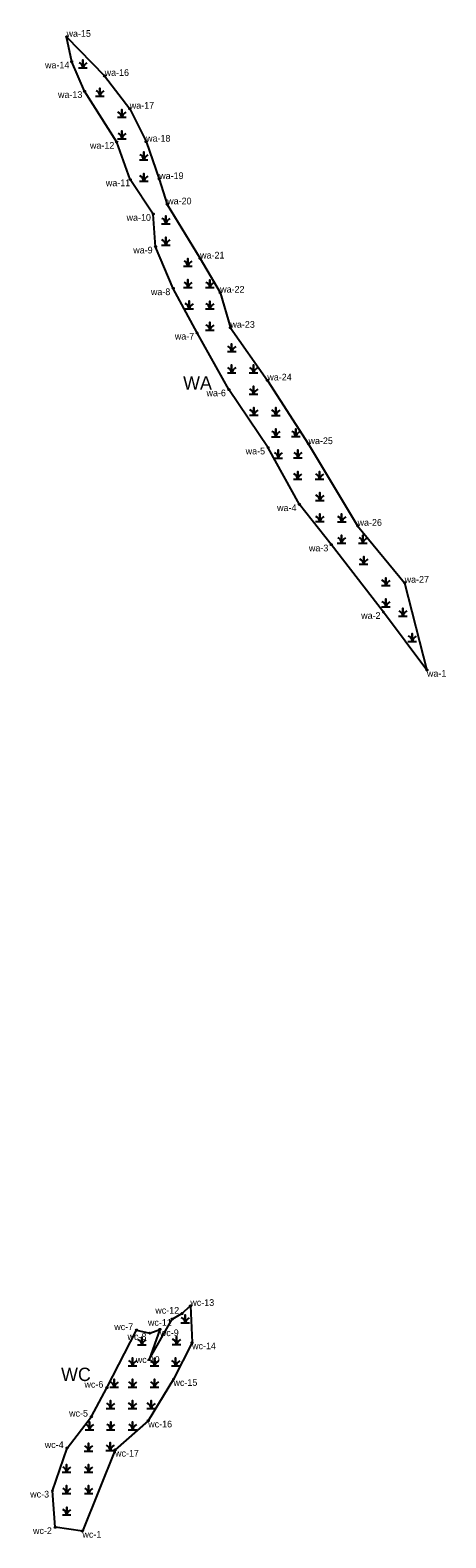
# Model space of a CAD drawing. Extents: x 1623201 to 1624143, y 886383 to 888508.
# Drawn here: x 1623832 to 1624143, y 886383 to 887511 of the extents above; entities that cross this region are included whole.
import ezdxf

# ---------------------------------------------------------------- set-up
doc = ezdxf.new("R2010")
doc.units = 0
for name, color, linetype in [('BR0168_Potential__x0020__Non__x002D__wetland__x0020__WOUS__x0020____x0028__Streams__x0029__', 7, 'Continuous'), ('BR0168_Potential__x0020__Non__x002D__wetland__x0020__WOUS__x0020____x0028__Surface__x0020__Waters__x0029__', 7, 'Continuous'), ('BR0168_Potential_Wetland_WOUS', 7, 'Continuous'), ('Default', 7, 'Continuous'), ('Exist Structure Major Bridge WW', 7, 'Continuous')]:
    doc.layers.add(name, color=color, linetype=linetype)

# ---------------------------------------------------------------- blocks, each defined once
blk = doc.blocks.new('SurveyPointCell')
at = {"layer": 'Default'}
for p, q in [((-0.5, 0), (0.5, 0)), ((0, -0.5), (0, 0.5))]:
    blk.add_line(p, q, dxfattribs=at)
blk.add_circle((0, 0), 0.5, dxfattribs=at)

msp = doc.modelspace()

# ---------------------------------------------------------------- linework, layer by layer
at = {"layer": 'BR0168_Potential_Wetland_WOUS'}
for points in [[(1624128.6, 887032.3), (1624096.1, 887075.6), (1624057, 887126.1), (1624033.2, 887156.2), (1624009.8, 887198.6), (1623980.5, 887242.1), (1623956.7, 887284.5), (1623938.8, 887317.7), (1623925.6, 887348.9), (1623923.9, 887373.3), (1623906.7, 887399.2), (1623896.5, 887427.2), (1623872.5, 887465.2), (1623862.9, 887487.3), (1623859, 887505.9), (1623887.5, 887476.7), (1623906.3, 887452.1), (1623918.5, 887427.5), (1623928.3, 887399.5), (1623934.3, 887380.6), (1623958.9, 887340.1), (1623973.9, 887314.6), (1623981.6, 887288.3), (1624009.2, 887248.9), (1624040, 887201.3), (1624076.7, 887140.2), (1624111.9, 887097.6)], [(1623870.9, 886388.4), (1623850.6, 886391.2), (1623848.5, 886418.5), (1623859.4, 886450.5), (1623877.6, 886474), (1623889.2, 886495.6), (1623911.4, 886538.7), (1623921.3, 886536.4), (1623928.8, 886539.2), (1623920.8, 886516.6), (1623938.1, 886546.9), (1623945.3, 886551), (1623951.6, 886556.8), (1623952.9, 886529.4), (1623939, 886502), (1623920.1, 886470.9), (1623895.3, 886449.1)]]:
    msp.add_lwpolyline(points, close=True, dxfattribs=at)
at = {"layer": 'Exist Structure Major Bridge WW'}
for points in [[(1623867.9, 887482.6), (1623871.2, 887482.6), (1623871.2, 887488.6), (1623871.2, 887482.6), (1623874.4, 887482.6)], [(1623880.6, 887461.6), (1623883.9, 887461.6), (1623883.9, 887467.5), (1623883.9, 887461.6), (1623887.1, 887461.6)], [(1623897.1, 887445.7), (1623900.3, 887445.7), (1623900.3, 887451.6), (1623900.3, 887445.7), (1623903.5, 887445.7)], [(1623897.1, 887429.7), (1623900.4, 887429.7), (1623900.4, 887435.6), (1623900.4, 887429.7), (1623903.6, 887429.7)], [(1623913.5, 887413.8), (1623916.7, 887413.8), (1623916.7, 887419.8), (1623916.7, 887413.8), (1623919.9, 887413.8)], [(1623913.5, 887397.9), (1623916.7, 887397.9), (1623916.7, 887403.8), (1623916.7, 887397.9), (1623920, 887397.9)], [(1623930, 887366.1), (1623933.2, 887366.1), (1623933.2, 887372), (1623933.2, 887366.1), (1623936.4, 887366.1)], [(1623930, 887350.1), (1623933.2, 887350.1), (1623933.2, 887356.1), (1623933.2, 887350.1), (1623936.4, 887350.1)], [(1623946.5, 887334.3), (1623949.7, 887334.3), (1623949.7, 887340.2), (1623949.7, 887334.3), (1623952.9, 887334.3)], [(1623946.4, 887318.3), (1623949.7, 887318.3), (1623949.7, 887324.3), (1623949.7, 887318.3), (1623952.9, 887318.3)], [(1623962.9, 887318.3), (1623966.1, 887318.3), (1623966.1, 887324.2), (1623966.1, 887318.3), (1623969.4, 887318.3)], [(1623947.4, 887302.5), (1623950.6, 887302.5), (1623950.6, 887308.4), (1623950.6, 887302.5), (1623953.9, 887302.5)], [(1623962.9, 887302.4), (1623966.1, 887302.4), (1623966.1, 887308.3), (1623966.1, 887302.4), (1623969.4, 887302.4)], [(1623962.9, 887286.4), (1623966.1, 887286.4), (1623966.1, 887292.4), (1623966.1, 887286.4), (1623969.3, 887286.4)], [(1623979.3, 887270.5), (1623982.5, 887270.5), (1623982.5, 887276.4), (1623982.5, 887270.5), (1623985.8, 887270.5)], [(1623979.3, 887254.6), (1623982.5, 887254.6), (1623982.5, 887260.5), (1623982.5, 887254.6), (1623985.7, 887254.6)], [(1623995.7, 887254.7), (1623998.9, 887254.7), (1623998.9, 887260.6), (1623998.9, 887254.7), (1624002.2, 887254.7)], [(1623995.7, 887238.7), (1623998.9, 887238.7), (1623998.9, 887244.6), (1623998.9, 887238.7), (1624002.2, 887238.7)], [(1623995.8, 887222.9), (1623999, 887222.9), (1623999, 887228.8), (1623999, 887222.9), (1624002.3, 887222.9)], [(1624012.3, 887222.8), (1624015.5, 887222.8), (1624015.5, 887228.7), (1624015.5, 887222.8), (1624018.8, 887222.8)], [(1624012.2, 887206.8), (1624015.5, 887206.8), (1624015.5, 887212.8), (1624015.5, 887206.8), (1624018.7, 887206.8)], [(1624027.2, 887206.9), (1624030.4, 887206.9), (1624030.4, 887212.8), (1624030.4, 887206.9), (1624033.7, 887206.9)], [(1624014.2, 887190.9), (1624017.4, 887190.9), (1624017.4, 887196.9), (1624017.4, 887190.9), (1624020.6, 887190.9)], [(1624028.7, 887191.1), (1624032, 887191.1), (1624032, 887197), (1624032, 887191.1), (1624035.2, 887191.1)], [(1624028.7, 887175), (1624031.9, 887175), (1624031.9, 887180.9), (1624031.9, 887175), (1624035.1, 887175)], [(1624045.1, 887175), (1624048.3, 887175), (1624048.3, 887180.9), (1624048.3, 887175), (1624051.5, 887175)], [(1624045.2, 887159.1), (1624048.4, 887159.1), (1624048.4, 887165), (1624048.4, 887159.1), (1624051.6, 887159.1)], [(1624045.2, 887143.3), (1624048.4, 887143.3), (1624048.4, 887149.2), (1624048.4, 887143.3), (1624051.6, 887143.3)], [(1624061.6, 887143.1), (1624064.8, 887143.1), (1624064.8, 887149.1), (1624064.8, 887143.1), (1624068.1, 887143.1)], [(1624061.5, 887127.3), (1624064.7, 887127.3), (1624064.7, 887133.2), (1624064.7, 887127.3), (1624067.9, 887127.3)], [(1624077.5, 887127.3), (1624080.7, 887127.3), (1624080.7, 887133.2), (1624080.7, 887127.3), (1624084, 887127.3)], [(1624078, 887111.4), (1624081.3, 887111.4), (1624081.3, 887117.3), (1624081.3, 887111.4), (1624084.5, 887111.4)], [(1624094.6, 887095.5), (1624097.8, 887095.5), (1624097.8, 887101.4), (1624097.8, 887095.5), (1624101, 887095.5)], [(1624094.5, 887079.6), (1624097.8, 887079.6), (1624097.8, 887085.5), (1624097.8, 887079.6), (1624101, 887079.6)], [(1624107.4, 887072.6), (1624110.6, 887072.6), (1624110.6, 887078.6), (1624110.6, 887072.6), (1624113.8, 887072.6)], [(1624114.3, 887053.8), (1624117.5, 887053.8), (1624117.5, 887059.7), (1624117.5, 887053.8), (1624120.7, 887053.8)], [(1623944.5, 886544.1), (1623947.7, 886544.1), (1623947.7, 886550), (1623947.7, 886544.1), (1623950.9, 886544.1)], [(1623912.1, 886527.6), (1623915.4, 886527.6), (1623915.4, 886533.5), (1623915.4, 886527.6), (1623918.6, 886527.6)], [(1623938, 886527.9), (1623941.2, 886527.9), (1623941.2, 886533.8), (1623941.2, 886527.9), (1623944.4, 886527.9)], [(1623905.2, 886512), (1623908.4, 886512), (1623908.4, 886517.9), (1623908.4, 886512), (1623911.6, 886512)], [(1623921.5, 886511.9), (1623924.8, 886511.9), (1623924.8, 886517.8), (1623924.8, 886511.9), (1623928, 886511.9)], [(1623937.4, 886511.9), (1623940.6, 886511.9), (1623940.6, 886517.9), (1623940.6, 886511.9), (1623943.9, 886511.9)], [(1623891.3, 886496), (1623894.6, 886496), (1623894.6, 886501.9), (1623894.6, 886496), (1623897.8, 886496)], [(1623905.1, 886496), (1623908.4, 886496), (1623908.4, 886501.9), (1623908.4, 886496), (1623911.6, 886496)], [(1623921.6, 886496), (1623924.8, 886496), (1623924.8, 886502), (1623924.8, 886496), (1623928, 886496)], [(1623888.7, 886480.1), (1623891.9, 886480.1), (1623891.9, 886486), (1623891.9, 886480.1), (1623895.2, 886480.1)], [(1623905.1, 886480.1), (1623908.3, 886480.1), (1623908.3, 886486), (1623908.3, 886480.1), (1623911.5, 886480.1)], [(1623919, 886480.1), (1623922.2, 886480.1), (1623922.2, 886486), (1623922.2, 886480.1), (1623925.5, 886480.1)], [(1623872.9, 886464.2), (1623876.2, 886464.2), (1623876.2, 886470.1), (1623876.2, 886464.2), (1623879.4, 886464.2)], [(1623888.8, 886464.2), (1623892, 886464.2), (1623892, 886470.1), (1623892, 886464.2), (1623895.2, 886464.2)], [(1623905.2, 886464.2), (1623908.4, 886464.2), (1623908.4, 886470.1), (1623908.4, 886464.2), (1623911.6, 886464.2)], [(1623872.2, 886448.2), (1623875.5, 886448.2), (1623875.5, 886454.2), (1623875.5, 886448.2), (1623878.7, 886448.2)], [(1623888.4, 886448.7), (1623891.6, 886448.7), (1623891.6, 886454.7), (1623891.6, 886448.7), (1623894.9, 886448.7)], [(1623855.8, 886432.4), (1623859, 886432.4), (1623859, 886438.3), (1623859, 886432.4), (1623862.3, 886432.4)], [(1623872.2, 886432.4), (1623875.5, 886432.4), (1623875.5, 886438.3), (1623875.5, 886432.4), (1623878.7, 886432.4)], [(1623855.8, 886416.5), (1623859, 886416.5), (1623859, 886422.4), (1623859, 886416.5), (1623862.3, 886416.5)], [(1623872.3, 886416.4), (1623875.5, 886416.4), (1623875.5, 886422.4), (1623875.5, 886416.4), (1623878.7, 886416.4)], [(1623855.9, 886400.5), (1623859.1, 886400.5), (1623859.1, 886406.4), (1623859.1, 886400.5), (1623862.3, 886400.5)]]:
    msp.add_lwpolyline(points, dxfattribs=at)
for centre, radius, start, end in [((1623866.6, 887482.3), 4.61, 4.1403, 67.535), ((1623878, 887480.4), 7.21, 122.1274, 161.6222), ((1623879.3, 887461.3), 4.61, 4.1403, 67.535), ((1623890.7, 887459.3), 7.21, 122.1274, 161.6222), ((1623895.7, 887445.3), 4.61, 4.1403, 67.535), ((1623907.1, 887443.4), 7.21, 122.1274, 161.6222), ((1623895.8, 887429.4), 4.61, 4.1403, 67.535), ((1623907.2, 887427.4), 7.21, 122.1274, 161.6222), ((1623912.1, 887413.5), 4.61, 4.1403, 67.535), ((1623923.6, 887411.6), 7.21, 122.1274, 161.6222), ((1623912.1, 887397.6), 4.61, 4.1403, 67.535), ((1623923.6, 887395.6), 7.21, 122.1274, 161.6222), ((1623928.6, 887365.8), 4.61, 4.1403, 67.535), ((1623940, 887363.8), 7.21, 122.1274, 161.6222), ((1623928.6, 887349.8), 4.61, 4.1403, 67.535), ((1623940, 887347.9), 7.21, 122.1274, 161.6222), ((1623945.1, 887333.9), 4.61, 4.1403, 67.535), ((1623956.5, 887332), 7.21, 122.1274, 161.6222), ((1623945.1, 887318), 4.61, 4.1403, 67.535), ((1623956.5, 887316.1), 7.21, 122.1274, 161.6222), ((1623961.5, 887318), 4.61, 4.1403, 67.535), ((1623973, 887316), 7.21, 122.1274, 161.6222), ((1623946, 887302.1), 4.61, 4.1403, 67.535), ((1623957.5, 887300.2), 7.21, 122.1274, 161.6222), ((1623961.5, 887302), 4.61, 4.1403, 67.535), ((1623973, 887300.1), 7.21, 122.1274, 161.6222), ((1623961.5, 887286.1), 4.61, 4.1403, 67.535), ((1623972.9, 887284.2), 7.21, 122.1274, 161.6222), ((1623977.9, 887270.2), 4.61, 4.1403, 67.535), ((1623989.4, 887268.3), 7.21, 122.1274, 161.6222), ((1623977.9, 887254.3), 4.61, 4.1403, 67.535), ((1623989.4, 887252.4), 7.21, 122.1274, 161.6222), ((1623994.3, 887254.3), 4.61, 4.1403, 67.535), ((1624005.8, 887252.4), 7.21, 122.1274, 161.6222), ((1623994.3, 887238.4), 4.61, 4.1403, 67.535), ((1624005.8, 887236.4), 7.21, 122.1274, 161.6222), ((1623994.4, 887222.6), 4.61, 4.1403, 67.535), ((1624005.9, 887220.6), 7.21, 122.1274, 161.6222), ((1624010.9, 887222.4), 4.61, 4.1403, 67.535), ((1624022.4, 887220.5), 7.21, 122.1274, 161.6222), ((1624010.9, 887206.5), 4.61, 4.1403, 67.535), ((1624022.3, 887204.6), 7.21, 122.1274, 161.6222), ((1624025.8, 887206.5), 4.61, 4.1403, 67.535), ((1624037.3, 887204.6), 7.21, 122.1274, 161.6222), ((1624012.8, 887190.6), 4.61, 4.1403, 67.535), ((1624024.2, 887188.7), 7.21, 122.1274, 161.6222), ((1624027.4, 887190.7), 4.61, 4.1403, 67.535), ((1624038.8, 887188.8), 7.21, 122.1274, 161.6222), ((1624027.3, 887174.7), 4.61, 4.1403, 67.535), ((1624038.7, 887172.7), 7.21, 122.1274, 161.6222), ((1624043.7, 887174.7), 4.61, 4.1403, 67.535), ((1624055.1, 887172.7), 7.21, 122.1274, 161.6222), ((1624043.8, 887158.8), 4.61, 4.1403, 67.535), ((1624055.2, 887156.8), 7.21, 122.1274, 161.6222), ((1624043.8, 887142.9), 4.61, 4.1403, 67.535), ((1624055.2, 887141), 7.21, 122.1274, 161.6222), ((1624060.2, 887142.8), 4.61, 4.1403, 67.535), ((1624071.7, 887140.9), 7.21, 122.1274, 161.6222), ((1624060.1, 887127), 4.61, 4.1403, 67.535), ((1624071.6, 887125), 7.21, 122.1274, 161.6222), ((1624076.1, 887127), 4.61, 4.1403, 67.535), ((1624087.6, 887125.1), 7.21, 122.1274, 161.6222), ((1624076.7, 887111), 4.61, 4.1403, 67.535), ((1624088.1, 887109.1), 7.21, 122.1274, 161.6222), ((1624093.2, 887095.2), 4.61, 4.1403, 67.535), ((1624104.6, 887093.2), 7.21, 122.1274, 161.6222), ((1624093.2, 887079.2), 4.61, 4.1403, 67.535), ((1624104.6, 887077.3), 7.21, 122.1274, 161.6222), ((1624106, 887072.3), 4.61, 4.1403, 67.535), ((1624117.4, 887070.4), 7.21, 122.1274, 161.6222), ((1624112.9, 887053.5), 4.61, 4.1403, 67.535), ((1624124.3, 887051.5), 7.21, 122.1274, 161.6222), ((1623943.1, 886543.7), 4.61, 4.1403, 67.535), ((1623954.5, 886541.8), 7.21, 122.1274, 161.6222), ((1623910.8, 886527.3), 4.61, 4.1403, 67.535), ((1623922.2, 886525.4), 7.21, 122.1274, 161.6222), ((1623936.6, 886527.6), 4.61, 4.1403, 67.535), ((1623948, 886525.6), 7.21, 122.1274, 161.6222), ((1623903.8, 886511.6), 4.61, 4.1403, 67.535), ((1623915.2, 886509.7), 7.21, 122.1274, 161.6222), ((1623920.2, 886511.6), 4.61, 4.1403, 67.535), ((1623931.6, 886509.6), 7.21, 122.1274, 161.6222), ((1623936, 886511.6), 4.61, 4.1403, 67.535), ((1623947.5, 886509.7), 7.21, 122.1274, 161.6222), ((1623890, 886495.7), 4.61, 4.1403, 67.535), ((1623901.4, 886493.7), 7.21, 122.1274, 161.6222), ((1623903.8, 886495.7), 4.61, 4.1403, 67.535), ((1623915.2, 886493.7), 7.21, 122.1274, 161.6222), ((1623920.2, 886495.7), 4.61, 4.1403, 67.535), ((1623931.6, 886493.8), 7.21, 122.1274, 161.6222), ((1623887.3, 886479.7), 4.61, 4.1403, 67.535), ((1623898.8, 886477.8), 7.21, 122.1274, 161.6222), ((1623903.7, 886479.7), 4.61, 4.1403, 67.535), ((1623915.2, 886477.8), 7.21, 122.1274, 161.6222), ((1623917.6, 886479.8), 4.61, 4.1403, 67.535), ((1623929.1, 886477.8), 7.21, 122.1274, 161.6222), ((1623871.6, 886463.9), 4.61, 4.1403, 67.535), ((1623883, 886462), 7.21, 122.1274, 161.6222), ((1623887.4, 886463.9), 4.61, 4.1403, 67.535), ((1623898.8, 886461.9), 7.21, 122.1274, 161.6222), ((1623903.8, 886463.9), 4.61, 4.1403, 67.535), ((1623915.2, 886461.9), 7.21, 122.1274, 161.6222), ((1623870.9, 886447.9), 4.61, 4.1403, 67.535), ((1623882.3, 886446), 7.21, 122.1274, 161.6222), ((1623887, 886448.4), 4.61, 4.1403, 67.535), ((1623898.5, 886446.5), 7.21, 122.1274, 161.6222), ((1623854.4, 886432), 4.61, 4.1403, 67.535), ((1623865.9, 886430.1), 7.21, 122.1274, 161.6222), ((1623870.9, 886432), 4.61, 4.1403, 67.535), ((1623882.3, 886430.1), 7.21, 122.1274, 161.6222), ((1623854.4, 886416.1), 4.61, 4.1403, 67.535), ((1623865.9, 886414.2), 7.21, 122.1274, 161.6222), ((1623870.9, 886416.1), 4.61, 4.1403, 67.535), ((1623882.3, 886414.2), 7.21, 122.1274, 161.6222), ((1623854.5, 886400.2), 4.61, 4.1403, 67.535), ((1623865.9, 886398.2), 7.21, 122.1274, 161.6222)]:
    msp.add_arc(centre, radius, start, end, dxfattribs=at)

# ---------------------------------------------------------------- block references
at = {"layer": 'BR0168_Potential_Wetland_WOUS'}
msp.add_blockref('SurveyPointCell', (1624128.6, 887032.3), dxfattribs=at)
at = {"layer": 'Default'}
for p in [(1623859, 887505.9), (1623862.9, 887487.3), (1623887.5, 887476.7), (1623872.5, 887465.2), (1623906.3, 887452.1), (1623896.5, 887427.2), (1623918.5, 887427.5), (1623906.7, 887399.2), (1623928.3, 887399.5), (1623934.3, 887380.6), (1623923.9, 887373.3), (1623925.6, 887348.9), (1623958.9, 887340.1), (1623938.8, 887317.7), (1623973.9, 887314.6), (1623956.7, 887284.5), (1623981.6, 887288.3), (1624009.2, 887248.9), (1623980.5, 887242.1), (1624040, 887201.3), (1624009.8, 887198.6), (1624033.2, 887156.2), (1624076.7, 887140.2), (1624057, 887126.1), (1624111.9, 887097.6), (1624096.1, 887075.6), (1623951.6, 886556.8), (1623938.1, 886546.9), (1623945.3, 886551), (1623911.4, 886538.7), (1623921.3, 886536.4), (1623928.8, 886539.2), (1623952.9, 886529.4), (1623920.8, 886516.6), (1623939, 886502), (1623889.2, 886495.6), (1623877.6, 886474), (1623920.1, 886470.9), (1623859.4, 886450.5), (1623895.3, 886449.1), (1623848.5, 886418.5), (1623850.6, 886391.2), (1623870.9, 886388.4)]:
    msp.add_blockref('SurveyPointCell', p, dxfattribs=at)

# ---------------------------------------------------------------- texts
at = {"layer": 'BR0168_Potential__x0020__Non__x002D__wetland__x0020__WOUS__x0020____x0028__Streams__x0029__'}
for s, p in [('WA', (1623946.2, 887242.1)), ('WC', (1623854.9, 886500.6))]:
    msp.add_text(s, height=10, dxfattribs=at).set_placement(p)
at = {"layer": 'BR0168_Potential__x0020__Non__x002D__wetland__x0020__WOUS__x0020____x0028__Surface__x0020__Waters__x0029__'}
for s, p in [('wa-15', (1623859, 887505.9)), ('wa-14', (1623842.9, 887482.3)), ('wa-16', (1623887.5, 887476.7)), ('wa-13', (1623852.6, 887460.2)), ('wa-17', (1623906.3, 887452.1)), ('wa-12', (1623876.5, 887422.2)), ('wa-18', (1623918.5, 887427.5)), ('wa-19', (1623928.3, 887399.5)), ('wa-11', (1623888.4, 887394.2)), ('wa-20', (1623934.3, 887380.6)), ('wa-10', (1623903.9, 887368.3)), ('wa-9', (1623908.9, 887343.9)), ('wa-21', (1623958.9, 887340.1)), ('wa-8', (1623922.1, 887312.7)), ('wa-22', (1623973.9, 887314.6)), ('wa-23', (1623981.6, 887288.3)), ('wa-7', (1623940, 887279.5)), ('wa-24', (1624009.2, 887248.9)), ('wa-6', (1623963.7, 887237.1)), ('wa-25', (1624040, 887201.3)), ('wa-5', (1623993, 887193.6)), ('wa-4', (1624016.5, 887151.2)), ('wa-26', (1624076.7, 887140.2)), ('wa-3', (1624040.3, 887121.1)), ('wa-27', (1624111.9, 887097.6)), ('wa-2', (1624079.4, 887070.6)), ('wa-1', (1624128.6, 887027.3)), ('wc-13', (1623951.6, 886556.8)), ('wc-11', (1623919.9, 886541.9)), ('wc-12', (1623925.4, 886551)), ('wc-7', (1623894.7, 886538.7)), ('wc-8', (1623904.6, 886531.4)), ('wc-9', (1623928.8, 886534.2)), ('wc-14', (1623952.9, 886524.4)), ('wc-10', (1623910.8, 886514.1)), ('wc-6', (1623872.4, 886495.6)), ('wc-15', (1623939, 886497)), ('wc-5', (1623860.9, 886474)), ('wc-16', (1623920.1, 886465.9)), ('wc-4', (1623842.7, 886450.5)), ('wc-17', (1623895.3, 886444.1)), ('wc-3', (1623831.8, 886413.5)), ('wc-2', (1623833.9, 886386.2)), ('wc-1', (1623870.9, 886383.4))]:
    msp.add_text(s, height=5, dxfattribs=at).set_placement(p)

doc.saveas('drawing.dxf')
